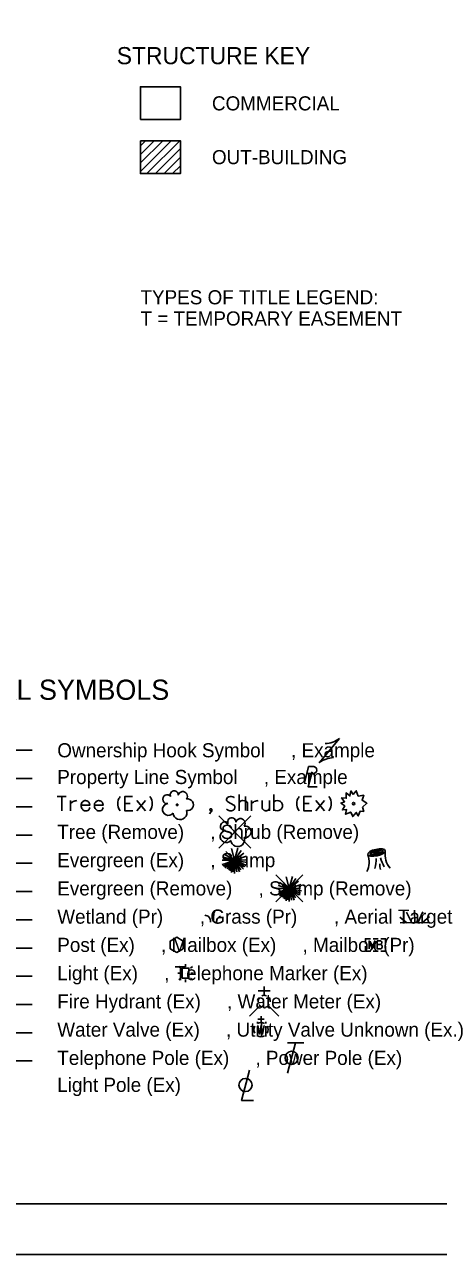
# Model space of a CAD drawing. Extents: x 0 to 34, y 0 to 22.
# Drawn here: x 8.19 to 12.3, y 0 to 12.19 of the extents above; entities that cross this region are included whole.
import ezdxf

# ---------------------------------------------------------------- set-up
doc = ezdxf.new("R2010")
doc.units = 0
for name, color, linetype in [('Default', 7, 'Continuous'), ('RW_X_Esmt_CH', 7, 'Continuous'), ('RW_X_Esmt_LA', 7, 'Continuous'), ('SC_Shading1', 7, 'Continuous'), ('SH_Border', 7, 'Continuous'), ('SH_Cut_Line', 7, 'Continuous'), ('SH_Text', 7, 'Continuous')]:
    doc.layers.add(name, color=color, linetype=linetype)

msp = doc.modelspace()

# ---------------------------------------------------------------- linework, layer by layer
at = {"layer": 'Default'}
msp.add_line((10.38, 4.538), (10.38, 4.399), dxfattribs=at)
at = {"layer": 'RW_X_Esmt_CH'}
msp.add_line((4.287, 3.597), (8.262, 3.597), dxfattribs=at)
at = {"layer": 'RW_X_Esmt_LA'}
msp.add_line((6.062, 4.157), (8.262, 4.157), dxfattribs=at)
at = {"layer": 'SC_Shading1'}
msp.add_lwpolyline([(9.338, 11.248), (9.735, 11.248), (9.735, 11.574), (9.338, 11.574)], close=True, dxfattribs=at)
at = {"layer": 'SH_Border'}
msp.add_lwpolyline([(2, 21.5), (33.5, 21.5), (33.5, 0.5), (2, 0.5)], close=True, dxfattribs=at)
at = {"layer": 'SH_Cut_Line'}
msp.add_lwpolyline([(0, 0), (34, 0), (34, 22), (0, 22)], close=True, dxfattribs=at)
at = {"layer": 'SH_Text'}
for p, q in [((9.338, 10.987), (9.389, 11.038)), ((9.338, 10.902), (9.474, 11.038)), ((9.338, 10.818), (9.559, 11.038)), ((9.338, 10.733), (9.644, 11.038)), ((9.402, 10.713), (9.728, 11.038)), ((9.487, 10.713), (9.735, 10.961)), ((9.572, 10.713), (9.735, 10.876)), ((9.656, 10.713), (9.735, 10.791)), ((11.112, 4.874), (11.312, 5.114)), ((6.205, 4.997), (8.262, 4.997)), ((11.212, 4.994), (11.212, 4.994)), ((10.989, 4.766), (11.053, 4.766)), ((3.644, 4.717), (8.262, 4.717)), ((11.029, 4.735), (11.029, 4.735)), ((8.512, 4.538), (8.599, 4.538)), ((8.556, 4.538), (8.556, 4.398)), ((10.316, 4.398), (10.316, 4.56)), ((10.663, 4.398), (10.663, 4.56)), ((4.211, 4.437), (8.262, 4.437)), ((8.643, 4.398), (8.643, 4.498)), ((9.182, 4.468), (9.236, 4.468)), ((9.302, 4.499), (9.386, 4.398)), ((9.302, 4.398), (9.386, 4.499)), ((10.441, 4.398), (10.441, 4.498)), ((10.619, 4.398), (10.619, 4.498)), ((10.959, 4.468), (11.013, 4.468)), ((11.079, 4.499), (11.163, 4.398)), ((11.079, 4.398), (11.163, 4.499)), ((10.114, 4.348), (10.434, 4.027)), ((10.434, 4.348), (10.114, 4.027)), ((10.274, 4.188), (10.274, 4.188)), ((10.272, 3.908), (10.241, 4.023)), ((10.272, 3.908), (10.303, 4.025)), ((10.148, 3.908), (10.272, 3.908)), ((10.272, 3.908), (10.161, 3.937)), ((10.272, 3.908), (10.164, 3.869)), ((10.272, 3.908), (10.172, 3.851)), ((10.272, 3.908), (10.174, 3.965)), ((10.272, 3.908), (10.174, 3.833)), ((10.272, 3.908), (10.184, 3.995)), ((10.272, 3.908), (10.198, 3.821)), ((10.272, 3.908), (10.214, 3.807)), ((10.272, 3.908), (10.23, 3.799)), ((10.272, 3.908), (10.24, 3.786)), ((10.272, 3.908), (10.258, 3.793)), ((10.272, 3.908), (10.338, 4.005)), ((10.272, 3.908), (10.363, 3.978)), ((10.272, 3.908), (10.39, 3.948)), ((10.272, 3.908), (10.384, 3.91)), ((10.272, 3.777), (10.272, 3.908)), ((10.272, 3.908), (10.295, 3.792)), ((10.272, 3.908), (10.32, 3.791)), ((10.272, 3.908), (10.335, 3.813)), ((10.272, 3.908), (10.361, 3.82)), ((10.272, 3.908), (10.367, 3.844)), ((10.272, 3.908), (10.383, 3.859)), ((10.272, 3.908), (10.392, 3.884)), ((11.7, 3.908), (11.7, 3.908)), ((4.988, 3.877), (8.262, 3.877)), ((10.681, 3.761), (10.948, 3.494)), ((10.948, 3.761), (10.681, 3.494)), ((10.814, 3.628), (10.704, 3.657)), ((10.814, 3.628), (10.717, 3.685)), ((10.814, 3.628), (10.727, 3.715)), ((10.814, 3.628), (10.783, 3.743)), ((10.814, 3.628), (10.846, 3.745)), ((10.814, 3.628), (10.881, 3.725)), ((10.814, 3.628), (10.906, 3.698)), ((10.814, 3.628), (10.933, 3.668)), ((10.691, 3.628), (10.814, 3.628)), ((10.814, 3.628), (10.707, 3.589)), ((10.814, 3.628), (10.715, 3.571)), ((10.814, 3.628), (10.717, 3.553)), ((10.814, 3.628), (10.741, 3.541)), ((10.814, 3.628), (10.756, 3.527)), ((10.814, 3.628), (10.773, 3.519)), ((10.814, 3.628), (10.783, 3.506)), ((10.814, 3.628), (10.801, 3.513)), ((10.814, 3.628), (10.927, 3.63)), ((10.814, 3.497), (10.814, 3.628)), ((10.814, 3.628), (10.837, 3.512)), ((10.814, 3.628), (10.863, 3.511)), ((10.814, 3.628), (10.878, 3.533)), ((10.814, 3.628), (10.904, 3.54)), ((10.814, 3.628), (10.91, 3.564)), ((10.814, 3.628), (10.926, 3.579)), ((10.814, 3.628), (10.935, 3.604)), ((10.814, 3.628), (10.814, 3.628)), ((12.06, 3.288), (12.058, 3.413)), ((6.067, 3.317), (8.262, 3.317)), ((11.981, 3.287), (11.913, 3.344)), ((12.03, 3.287), (11.978, 3.393)), ((12.09, 3.288), (12.139, 3.396)), ((12.138, 3.289), (12.205, 3.348)), ((11.914, 3.286), (12.206, 3.29)), ((11.646, 3.129), (11.696, 3.129)), ((11.671, 3.068), (11.671, 3.068)), ((4.506, 3.037), (8.262, 3.037)), ((11.646, 3.007), (11.696, 3.007)), ((9.738, 2.836), (9.719, 2.855)), ((9.786, 2.852), (9.786, 2.878)), ((9.853, 2.855), (9.834, 2.836)), ((4.778, 2.757), (8.262, 2.757)), ((9.734, 2.788), (9.707, 2.788)), ((9.738, 2.739), (9.719, 2.721)), ((9.786, 2.788), (9.786, 2.788)), ((9.786, 2.724), (9.786, 2.697)), ((9.853, 2.721), (9.834, 2.739)), ((9.865, 2.788), (9.838, 2.788)), ((10.625, 2.611), (10.505, 2.611)), ((10.565, 2.568), (10.565, 2.654)), ((4.778, 2.477), (8.262, 2.477)), ((10.523, 2.465), (10.419, 2.361)), ((10.565, 2.508), (10.565, 2.508)), ((10.565, 2.508), (10.565, 2.508)), ((10.608, 2.465), (10.712, 2.361)), ((10.566, 2.33), (10.502, 2.33)), ((10.534, 2.298), (10.534, 2.361)), ((4.778, 2.197), (8.262, 2.197)), ((10.534, 2.228), (10.534, 2.228)), ((10.958, 2.098), (10.798, 2.098)), ((10.878, 2.098), (10.798, 1.798)), ((4.778, 1.917), (8.262, 1.917))]:
    msp.add_line(p, q, dxfattribs=at)
for points in [[(9.338, 11.038), (9.735, 11.038), (9.735, 10.713), (9.338, 10.713)], [(9.753, 2.738), (9.819, 2.738), (9.819, 2.838), (9.753, 2.838)]]:
    msp.add_lwpolyline(points, close=True, dxfattribs=at)
for points in [[(10.968, 4.686), (11.007, 4.835), (11.058, 4.835)], [(11.042, 4.783), (11.002, 4.635), (11.09, 4.635)], [(9.136, 4.538), (9.128, 4.527), (9.122, 4.518), (9.117, 4.503), (9.114, 4.483), (9.114, 4.452), (9.116, 4.435), (9.122, 4.418), (9.129, 4.406), (9.136, 4.398)], [(9.258, 4.538), (9.182, 4.538), (9.182, 4.398), (9.263, 4.398)], [(9.431, 4.538), (9.439, 4.527), (9.444, 4.518), (9.45, 4.503), (9.453, 4.483), (9.453, 4.452), (9.451, 4.435), (9.444, 4.418), (9.438, 4.406), (9.431, 4.398)], [(10.269, 4.528), (10.266, 4.53), (10.263, 4.532), (10.253, 4.536), (10.241, 4.538), (10.232, 4.538), (10.229, 4.538), (10.215, 4.534), (10.203, 4.528), (10.195, 4.519), (10.193, 4.51), (10.193, 4.504), (10.195, 4.495), (10.204, 4.487), (10.264, 4.454), (10.27, 4.45), (10.272, 4.445), (10.274, 4.439), (10.274, 4.432), (10.273, 4.425), (10.272, 4.421), (10.27, 4.415), (10.268, 4.411), (10.265, 4.408), (10.262, 4.404), (10.259, 4.402), (10.254, 4.4), (10.251, 4.399), (10.241, 4.398), (10.226, 4.398), (10.216, 4.4), (10.201, 4.408), (10.193, 4.414)], [(10.912, 4.538), (10.905, 4.527), (10.899, 4.518), (10.894, 4.503), (10.89, 4.483), (10.89, 4.452), (10.893, 4.435), (10.899, 4.418), (10.906, 4.406), (10.912, 4.398)], [(11.035, 4.538), (10.959, 4.538), (10.959, 4.398), (11.04, 4.398)], [(11.208, 4.538), (11.216, 4.527), (11.221, 4.518), (11.227, 4.503), (11.23, 4.483), (11.23, 4.452), (11.228, 4.435), (11.221, 4.418), (11.214, 4.406), (11.208, 4.398)], [(11.449, 4.558), (11.479, 4.595), (11.5, 4.542), (11.554, 4.551), (11.537, 4.501), (11.585, 4.471), (11.542, 4.434), (11.554, 4.389), (11.517, 4.392), (11.5, 4.346), (11.479, 4.381), (11.445, 4.34), (11.424, 4.384), (11.373, 4.363), (11.382, 4.41), (11.342, 4.406), (11.365, 4.445), (11.327, 4.474), (11.364, 4.487), (11.334, 4.527), (11.38, 4.522), (11.379, 4.574), (11.416, 4.545), (11.427, 4.594), (11.449, 4.558)], [(8.643, 4.465), (8.648, 4.473), (8.655, 4.479), (8.661, 4.484), (8.669, 4.488), (8.681, 4.493), (8.69, 4.496), (8.697, 4.497), (8.707, 4.498)], [(8.749, 4.452), (8.835, 4.452), (8.833, 4.468), (8.829, 4.475), (8.826, 4.482), (8.82, 4.487), (8.815, 4.491), (8.807, 4.495), (8.799, 4.497), (8.792, 4.498), (8.787, 4.498), (8.778, 4.496), (8.766, 4.489), (8.758, 4.48), (8.754, 4.476), (8.751, 4.468), (8.749, 4.46), (8.749, 4.441), (8.751, 4.431), (8.756, 4.42), (8.762, 4.412), (8.767, 4.406), (8.775, 4.4), (8.782, 4.398), (8.794, 4.398), (8.805, 4.398), (8.815, 4.4), (8.821, 4.403), (8.825, 4.407), (8.829, 4.413), (8.833, 4.421), (8.835, 4.43)], [(8.881, 4.452), (8.967, 4.452), (8.965, 4.468), (8.961, 4.475), (8.958, 4.482), (8.953, 4.487), (8.947, 4.491), (8.939, 4.495), (8.932, 4.497), (8.924, 4.498), (8.92, 4.498), (8.911, 4.496), (8.899, 4.489), (8.89, 4.48), (8.887, 4.476), (8.883, 4.468), (8.881, 4.46), (8.881, 4.441), (8.883, 4.431), (8.889, 4.42), (8.894, 4.412), (8.9, 4.406), (8.907, 4.4), (8.914, 4.398), (8.926, 4.398), (8.937, 4.398), (8.947, 4.4), (8.954, 4.403), (8.957, 4.407), (8.961, 4.413), (8.965, 4.421), (8.967, 4.43)], [(10.046, 4.399), (10.042, 4.398), (10.035, 4.398), (10.031, 4.4), (10.03, 4.401), (10.027, 4.404), (10.027, 4.407), (10.027, 4.41), (10.028, 4.413), (10.031, 4.415), (10.032, 4.417), (10.035, 4.418), (10.039, 4.418), (10.042, 4.417), (10.044, 4.415), (10.045, 4.414), (10.047, 4.411), (10.047, 4.409), (10.047, 4.404), (10.046, 4.398), (10.043, 4.39), (10.037, 4.382), (10.024, 4.367)], [(10.316, 4.474), (10.321, 4.482), (10.326, 4.488), (10.332, 4.493), (10.338, 4.496), (10.348, 4.498), (10.355, 4.499), (10.373, 4.497), (10.383, 4.493), (10.39, 4.488), (10.397, 4.482), (10.4, 4.474), (10.4, 4.398)], [(10.441, 4.465), (10.446, 4.473), (10.453, 4.479), (10.458, 4.484), (10.467, 4.488), (10.479, 4.493), (10.488, 4.496), (10.495, 4.497), (10.505, 4.498)], [(10.546, 4.498), (10.546, 4.422), (10.549, 4.418), (10.552, 4.412), (10.555, 4.409), (10.561, 4.404), (10.566, 4.401), (10.572, 4.399), (10.578, 4.398), (10.585, 4.398), (10.587, 4.398), (10.594, 4.399), (10.599, 4.401), (10.604, 4.403), (10.608, 4.407), (10.613, 4.411), (10.616, 4.415), (10.619, 4.422)], [(10.663, 4.486), (10.668, 4.49), (10.679, 4.496), (10.695, 4.498), (10.71, 4.496), (10.721, 4.491), (10.726, 4.489), (10.734, 4.484), (10.737, 4.479), (10.74, 4.474), (10.745, 4.465), (10.747, 4.457), (10.747, 4.446), (10.746, 4.437), (10.742, 4.424), (10.733, 4.412), (10.724, 4.406), (10.711, 4.4), (10.695, 4.398), (10.678, 4.4), (10.669, 4.404), (10.663, 4.409)], [(9.633, 3.03), (9.698, 2.993), (9.763, 3.03), (9.763, 3.105), (9.698, 3.143), (9.633, 3.105), (9.633, 3.03)], [(11.571, 3.08), (11.571, 3.129), (11.62, 3.129)], [(11.62, 3.007), (11.571, 3.007), (11.571, 3.055)], [(11.607, 3.028), (11.607, 3.108), (11.636, 3.028), (11.663, 3.108), (11.663, 3.028)], [(11.722, 3.071), (11.726, 3.074), (11.728, 3.076), (11.729, 3.078), (11.729, 3.079), (11.731, 3.082), (11.731, 3.084), (11.733, 3.088), (11.733, 3.09), (11.733, 3.093), (11.732, 3.096), (11.731, 3.1), (11.729, 3.102), (11.726, 3.105), (11.723, 3.106), (11.722, 3.107), (11.719, 3.108), (11.688, 3.108), (11.688, 3.028), (11.722, 3.028), (11.727, 3.03), (11.731, 3.033), (11.734, 3.039), (11.736, 3.044), (11.736, 3.05), (11.736, 3.054), (11.735, 3.057), (11.733, 3.063), (11.729, 3.067), (11.722, 3.071), (11.688, 3.071)], [(11.722, 3.129), (11.771, 3.129), (11.771, 3.08)], [(11.771, 3.055), (11.771, 3.007), (11.722, 3.007)], [(10.502, 2.269), (10.518, 2.183), (10.534, 2.269), (10.55, 2.183), (10.566, 2.269)], [(10.42, 1.827), (10.341, 1.527), (10.459, 1.527)]]:
    msp.add_lwpolyline(points, dxfattribs=at)
for centre, radius in [((9.702, 4.456), 0.0072), ((11.453, 4.468), 0.0115), ((10.274, 4.188), 0.0072), ((10.838, 1.948), 0.065), ((10.38, 1.679), 0.065)]:
    msp.add_circle(centre, radius, dxfattribs=at)
for centre, radius, start, end in [((11.154, 5.329), 0.267, 273.6945, 306.337), ((11.271, 4.659), 0.267, 93.6945, 126.337), ((11.053, 4.801), 0.0345, 270.471, 81.3281), ((9.603, 4.512), 0.0441, 39.0625, 279.5412), ((9.673, 4.557), 0.0395, 354.0047, 205.9741), ((9.757, 4.541), 0.0466, 323.83, 165.0376), ((9.806, 4.457), 0.0574, 259.1453, 101.4596), ((9.616, 4.41), 0.0592, 96.1722, 320.5737), ((9.73, 4.378), 0.0685, 184.9476, 19.4572), ((10.175, 4.244), 0.0441, 39.0625, 279.5412), ((10.244, 4.289), 0.0395, 354.0047, 205.9741), ((10.329, 4.273), 0.0466, 323.83, 165.0376), ((10.188, 4.141), 0.0592, 96.1722, 320.5737), ((10.378, 4.189), 0.0574, 259.1453, 101.4596), ((10.302, 4.11), 0.0685, 184.9476, 19.4572), ((11.408, 3.89), 0.2, 331.5338, 20.9269), ((11.424, 3.909), 0.253, 340.7938, 3.5481), ((12.025, 4.011), 0.316, 194.9653, 212.1216), ((11.98, 3.965), 0.215, 171.4106, 219.9194), ((11.895, 3.868), 0.182, 178.7926, 197.1224), ((10.565, 2.508), 0.06, 68.1395, 112.038), ((10.565, 2.508), 0.06, 140.021, 184.0629), ((10.565, 2.508), 0.06, 211.8788, 255.8479), ((10.565, 2.508), 0.06, 283.8239, 329.9097), ((10.565, 2.508), 0.06, 356.0165, 39.9889), ((10.534, 2.228), 0.07, 150.0184, 209.9816), ((10.534, 2.228), 0.07, 60.0184, 120.0157), ((10.534, 2.228), 0.07, 330.0184, 29.9816), ((10.534, 2.228), 0.07, 239.9843, 299.9816)]:
    msp.add_arc(centre, radius, start, end, dxfattribs=at)
for major_axis in [(0.0868, 0.0187), (0.0651, 0.0141), (0.0488, 0.0105), (0.0275, 0.0059), (0.0154, 0.0033)]:
    msp.add_ellipse((11.681, 3.983), major_axis=major_axis, ratio=0.36865, dxfattribs=at)
for points in [[(9.975, 3.363), (10.017, 3.346), (10.034, 3.292)], [(10.063, 3.296), (10.063, 3.344), (10.069, 3.388), (10.077, 3.409)], [(10.09, 3.289), (10.102, 3.328), (10.132, 3.351)]]:
    msp.add_spline(points, degree=3, dxfattribs=at)

# ---------------------------------------------------------------- texts
for s, height, p in [('STRUCTURE KEY', 0.17, (9.102, 11.797)), ('COMMERCIAL', 0.14, (10.047, 11.339)), ('OUT-BUILDING', 0.14, (10.047, 10.806)), ('TYPES OF TITLE LEGEND:', 0.14, (9.338, 9.417)), ('T = TEMPORARY EASEMENT', 0.14, (9.338, 9.207)), ('CONVENTIONAL SYMBOLS', 0.2, (6.146, 5.497)), ('Ownership Hook Symbol     , Example', 0.14, (8.512, 4.927)), ('Property Line Symbol     , Example', 0.14, (8.512, 4.662)), ('Tree (Remove)     , Shrub (Remove)', 0.14, (8.512, 4.118)), ('Evergreen (Ex)     , Stump ', 0.14, (8.512, 3.838)), ('Evergreen (Remove)     , Stump (Remove)', 0.14, (8.512, 3.558)), ('Wetland (Pr)       , Grass (Pr)       , Aerial Target    ', 0.14, (8.512, 3.278)), ('Post (Ex)     , Mailbox (Ex)     , Mailbox (Pr)', 0.14, (8.512, 2.998)), ('Light (Ex)     , Telephone Marker (Ex)     ', 0.14, (8.512, 2.718)), ('Fire Hydrant (Ex)     , Water Meter (Ex)', 0.14, (8.512, 2.438)), ('Water Valve (Ex)     , Utility Valve Unknown (Ex.)', 0.14, (8.512, 2.158)), ('Telephone Pole (Ex)     , Power Pole (Ex)', 0.14, (8.512, 1.878)), ('Light Pole (Ex)     ', 0.14, (8.512, 1.611))]:
    msp.add_text(s, height=height, dxfattribs=at).set_placement(p)

doc.saveas('drawing.dxf')
